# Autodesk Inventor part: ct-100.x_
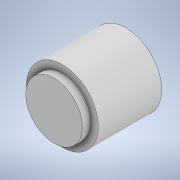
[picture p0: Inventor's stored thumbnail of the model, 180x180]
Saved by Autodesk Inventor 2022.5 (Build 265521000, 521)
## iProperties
Created: 2023-06
Part Number: ct-100.x_
Material: Generic
Document SubType Name: Modeling
Designer: ImaoCorp
Density: 1 g/cm^3
Appearance: Default
Sending System: SOLIDWORKS 2021-2021301
MC: AMD64
MC_MODEL: Intel64 Family 6 Model 60 Stepping 3, GenuineIntel
OS: Windows_NT
FRU: Parasolid Version 32.1, build 255,  1- 1-2021
FORMAT: text
GUISE: transmit
KEY: ct-100
FILE: ct-100.x_t
DATE: Thu Jun 15 15:47:31 2023
Author: ImaoCorp
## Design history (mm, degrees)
feature "Base1"
node "ソリッド1"
